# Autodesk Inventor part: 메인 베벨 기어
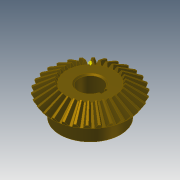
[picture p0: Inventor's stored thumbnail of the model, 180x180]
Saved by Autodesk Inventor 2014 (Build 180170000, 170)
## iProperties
Created: 2014-10
Part Number: 메인 베벨 기어
Material: Steel, Mild
Document SubType Name: Modeling
Designer: KYOUNG IL JANG
Categories: <?xml version="1.0" encoding="UTF-16"?> <MemberInstance><Categories><FamilyTemplate><FamilyTemplateParameter ValueType="xs:double" Id="1" ObjectReferenceKey="da
Mass: 269.583 g
Surface Area: 108.837 cm^2
Volume: 34.2981 cm^3
Density: 7.86 g/cm^3
Appearance: 얼룩무늬
CustomPartVersion: 1
Company: 한국ATC센터
Author: KYOUNG IL JANG
Revision Number: 1
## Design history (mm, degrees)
node "맨 위 점"
node "메쉬 평면2"
sketch "톱니 본체 스케치"
  geometry: L1 (0, 0)-(28.669, -21.997); L2 (28.669, -21.997)-(31.109, -18.336); L3 (31.109, -18.336)-(0, 0); L4 (30, -20)-(0, 0); L5 (17.219, -13.212)-(18.685, -11.013); L6 (28.669, -21.997)-(17.219, -13.212); L7 (31.109, -18.336)-(18.685, -11.013); L8 (0, -39.387)-(0, 6.564) reference; L9 (0, -20)-(31.109, -20)
  constraints: 16 end point, 4 point on line, 3 perpendicular, 2 collinear, 1 horizontal alignment, 1 vertical alignment
  dimensions: "d0" = 60 diameter of L4.start L8 (= da_de); "d1" = 57.33744 diameter of L1.end L8 (= da_dfe); "d2" = 62.2188 diameter of L2.end L8 (= da_dae); "d3" = 14.4 distance between parallel lines of L2 L5 (= da_b); "d4" = 18.3359 vertical distance of L2.end L1.start (= da_ve)
revolve "톱니 본체" sketch "톱니 본체 스케치" stored, may be unused: angle "d5" = 90 deg
node "시작점"
node "톱니 평면"
sketch "시작 스케치"
  geometry: L1 (0, -23.505)-(0, 10.645) reference; L2 (-0.709, -2.928)-(0.709, -2.928); A1 r 19.188 centre (-19.457, -7.014) between (-0.709, -2.928) and (-3.232, 3.229); A2 r 19.188 centre (19.457, -7.014) between (3.232, 3.229) and (0.709, -2.928); A3 r 57.403 centre (0, -54.083) between (3.232, 3.229) and (-3.232, 3.229); 1 further point
  constraints: 6 point on circle, 3 centre point, 3 symmetric about line, 2 end point, 1 coincident, 1 perpendicular, 1 other
  dimensions: "d7" = 19.18795 radius of A1 (= fd_rr); "d8" = 19.45712 horizontal distance of point (0, -54.083) A1.centre (= fd_x); "d9" = 47.06905 vertical distance of point (0, -54.083) A1.centre (= fd_y); "d57" = 57.40327 radius of A3 (= 0.5 x fd_dva + 0.3 x da_he); "d58" = 51.15527 distance from line of A3.centre L2 (= 0.5 x fd_dva - 1.12 x da_he)
node "끝점"
  node "끝 평면"
sketch "3D 스케치 오른쪽"
  node "Helical Curve Right" dims "d65" = 229.90621 (computed from da_dm, da_delta, da_beta), "d66" = 31.5, "d67" = 60 (= da_de), "d68" = -9.82794 (= -da_delta), "d69" = 8.10972 (computed from fd_loft, da_delta)
node "끝 평면 오른쪽"
sketch "끝 스케치 오른쪽"
  geometry: L1 (0, -41.54)-(0, 13.178) reference; L2 (-0.422, -1.69)-(0.422, -1.69); A1 r 11.427 centre (-11.587, -4.123) between (-0.422, -1.69) and (-1.925, 1.977); A2 r 11.427 centre (11.587, -4.123) between (1.925, 1.977) and (0.422, -1.69); A3 r 34.184 centre (0, -32.153) between (1.925, 1.977) and (-1.925, 1.977); 1 further point
  constraints: 6 point on circle, 3 centre point, 3 symmetric about line, 2 end point, 1 coincident, 1 perpendicular, 1 other
  dimensions: "d70" = 11.58699 horizontal distance of A3.centre A1.centre (computed from fd_x, fd_ratio); "d71" = 28.03028 vertical distance of point (0, -32.153) A1.centre (computed from fd_y, fd_ratio); "d72" = 11.4267 radius of A1 (computed from fd_rr, fd_ratio); "d73" = 30.46369 distance from line of point (0, -32.153) L2 (computed from d58, fd_ratio); "d74" = 34.18446 radius of A3 (computed from d57, fd_ratio)
feature "로프트 오른쪽" sketch "끝 스케치 오른쪽" dims "d75" = 0, "d77" = 0, "d79" = 0, "d80" = 90 deg, "d85" = 20, "d92" = 90 deg, "d93" = 90 deg, "da_teethtype" = 0 [user parameter]
sketch "3D 스케치 왼쪽"
  node "Helical Curve Left" dims "d26" = 229.90621 (computed from da_dm, da_delta, da_beta), "d27" = 8.10972 (computed from fd_loft, da_delta), "d28" = 60 (= da_de), "d29" = -9.82794 (= -da_delta)
node "끝 평면 왼쪽"
sketch "끝 스케치 왼쪽" dims "d56" = 10.3728 (derived)
  geometry: L1 (0, -43.753)-(0, 15.405) reference; L2 (-0.422, -1.678)-(0.422, -1.678); A1 r 11.427 centre (-11.587, -4.111) between (-0.422, -1.678) and (-1.925, 1.988); A2 r 11.427 centre (11.587, -4.111) between (1.925, 1.988) and (0.422, -1.678); A3 r 34.184 centre (0, -32.142) between (1.925, 1.988) and (-1.925, 1.988); 2 further points; 1 other entity
  constraints: 6 point on circle, 3 centre point, 3 symmetric about line, 2 end point, 1 coincident, 2 other
  dimensions: "d30" = 11.4267 radius of A1 (computed from fd_rr, fd_ratio); "d31" = 11.58699 horizontal distance of point (0, -32.142) A1.centre (computed from fd_x, fd_ratio); "d32" = 28.03028 vertical distance of A1.centre point (0, -32.142) (computed from fd_y, fd_ratio); "d61" = 34.18446 radius of A3 (computed from d57, fd_ratio); "d62" = 30.46369 distance from line of point (0, -32.142) L2 (computed from d58, fd_ratio)
feature "로프트 왼쪽" sketch "끝 스케치 왼쪽" dims "d35" = 0, "d37" = 0, "d39" = 0, "d40" = 90 deg, "d84" = 10, "d90" = 90 deg, "d91" = 90 deg, "da_teethtype" = 0 [user parameter]
sketch "본체 스케치"
  geometry: L1 (0, -35.038)-(0, -19.531) reference; L2 (28.669, -21.997)-(17.219, -13.212) reference; L3 (17.219, -13.212)-(0, -13.212); L4 (28.669, -21.997)-(0, -21.997)
  constraints: 4 end point, 2 perpendicular, 2 point on line
revolve "본체 고정" sketch "본체 스케치" stored, may be unused: angle "d46" = 90 deg
feature "피치 지름" dims angle "d47" = 90 deg
sketch "스케치8"
  geometry: C1 r 22.5 at (0, 0); 1 further point
  constraints: 1 centre point, 1 coincident
  dimensions: "d94" = 45 diameter of C1
extrude "돌출1" join sketch "스케치8" distance "d95" = 13; taper "d96" = 0 deg
sketch "스케치9"
  geometry: 1 further point
hole "구멍1" sketch "스케치9" at (0, 0) diameter "d97" = 17; stored, may be unused: countersink angle "d101" = 90 deg, drill point angle "d103" = 118 deg; dims "d98" = 6, "d99" = 4, "d100" = 2, "d102" = 8
sketch "스케치10"
  geometry: L1 (8.124, 2.5)-(10.8, 2.5); L2 (10.8, 2.5)-(10.8, -2.5); L3 (10.8, -2.5)-(8.124, -2.5); A1 r 8.5 centre (0, 0) between (8.124, 2.5) and (8.124, -2.5) reference; 1 further point
  constraints: 6 end point, 2 parallel, 2 point on circle, 1 horizontal, 1 perpendicular
  dimensions: "d104" = 5 distance of L1.end L2.end; "d112" = 19.3 dimension on A1 L2
extrude "돌출2" cut sketch "스케치10" stored distance "d106" = 10; taper "d107" = 0 deg
chamfer "모따기1" distance "d108" = 1; stored, may be unused: second distance "d109" = 2, angle "d110" = 45 deg
fillet "모깎기1" dims "d111" = 2
body "Solid1"
feature "로프트" dims "d17" = 0, "d18" = 90 deg, "d19" = 0, "d20" = 90 deg, "d89" = 0, "da_teethtype" = 0 [user parameter]
pattern_circular "원형 패턴" dims angle "d22" = 360 deg, "d88" = 0, "da_teethtype" = 0 [user parameter]
pattern_circular "원형 패턴 오른쪽" dims angle "d82" = 360 deg, "da_teethtype" = 0 [user parameter]
pattern_circular "원형 패턴 왼쪽" dims angle "d42" = 360 deg, "da_teethtype" = 0 [user parameter]
sketch "끝 스케치"
  geometry: L1 (0, -15.359)-(0, 6.983) reference; L2 (-0.422, -1.69)-(0.422, -1.69); A1 r 11.427 centre (-11.587, -4.123) between (-0.422, -1.69) and (-1.925, 1.977); A2 r 11.427 centre (11.587, -4.123) between (1.925, 1.977) and (0.422, -1.69); A3 r 34.184 centre (0, -32.153) between (1.925, 1.977) and (-1.925, 1.977); 1 further point
  constraints: 6 point on circle, 3 centre point, 3 symmetric about line, 2 end point, 1 coincident, 1 other
  dimensions: "d12" = 11.4267 radius of A1 (computed from fd_rr, fd_ratio); "d15" = 11.58699 horizontal distance of A1.centre point (0, -32.153) (computed from fd_x, fd_ratio); "d16" = 28.03028 vertical distance of A1.centre point (0, -32.153) (computed from fd_y, fd_ratio); "d59" = 34.18446 radius of A3 (computed from d57, fd_ratio); "d60" = 30.46369 distance from line of A3.centre L2 (computed from d58, fd_ratio)
sketch "Sketch6"
  geometry: L1 (30, -20)-(0, 0) reference; L2 (0, -37.8)-(0, 6.3) reference
body "Srf1"
other parameters: "da_b" = 14.4 [user parameter; used in 2 equation terms], "da_de" = 60 [user parameter; used in 4 equation terms], "da_dae" = 62.2188 [user parameter; used in 2 equation terms], "da_dfe" = 57.33744 [user parameter; used in 1 equation term], "da_le" = 36.05551 [user parameter; used in 1 equation term], "da_omega" = 90 deg [user parameter; used in 1 equation term], "da_beta" = 0 [user parameter; used in 2 equation terms], "da_delta" = 9.82794 [user parameter; used in 8 equation terms], "da_alpha" = 20 deg [user parameter; used in 2 equation terms], "da_he" = 4.4 [user parameter; used in 4 equation terms], "da_ve" = 18.3359 [user parameter; used in 1 equation term], "fd_dv" = 108.16654 (computed from da_de, da_delta) [user parameter; used in 1 equation term], "fd_dva" = 112.16654 (computed from da_dae, da_delta) [user parameter; used in 3 equation terms], "fd_dvb" = 101.6433 (computed from fd_dv, da_alpha) [user parameter; used in 2 equation terms], "da_zv" = 540.83269 [user parameter; used in 1 equation term], "fd_loft" = 14.62 (= da_b + 0.05 x da_he) [user parameter; used in 4 equation terms], "fd_ratio" = 5.95514 (computed from da_le, fd_loft) [user parameter; used in 15 equation terms], "fd_rr" = 19.18795 (computed from fd_dd, fd_dvb) [user parameter; used in 6 equation terms], "fd_angle" = 0.29367 (computed from da_zv) [user parameter; used in 4 equation terms], "fd_x1" = 1.58802 (computed from da_dvw, fd_angle) [user parameter; used in 1 equation term], "fd_y1" = 54.05995 (computed from da_dvw, fd_angle) [user parameter; used in 1 equation term], "fd_x2" = 17.8691 (computed from fd_rr, fd_angle2, fd_angle) [user parameter; used in 1 equation term], "fd_y2" = 6.9909 (computed from fd_rr, fd_angle2, fd_angle) [user parameter; used in 1 equation term], "fd_x" = 19.45712 (= fd_x1 + fd_x2) [user parameter; used in 4 equation terms], "fd_y" = 47.06905 (= fd_y1 - fd_y2) [user parameter; used in 4 equation terms], "fd_angle2" = 3.43555 (computed from fd_dvb, fd_dd, da_alpha) [user parameter; used in 2 equation terms], "fd_dd" = 108.64654 (= fd_dva - 0.8 x da_he) [user parameter; used in 2 equation terms], "da_dvw" = 108.16654 [user parameter; used in 2 equation terms], "d11" = 14.62 (= fd_loft), "da_dm" = 48.01848 [user parameter; used in 2 equation terms], "da_x" = 0 [user parameter], "da_m" = 2 [user parameter], "d48" = 0, "d49" = 0, "d50" = 90 deg (= da_omega), "d51" = 6 deg (computed from da_z), "d52" = 0, "d53" = 0, "d54" = 0
